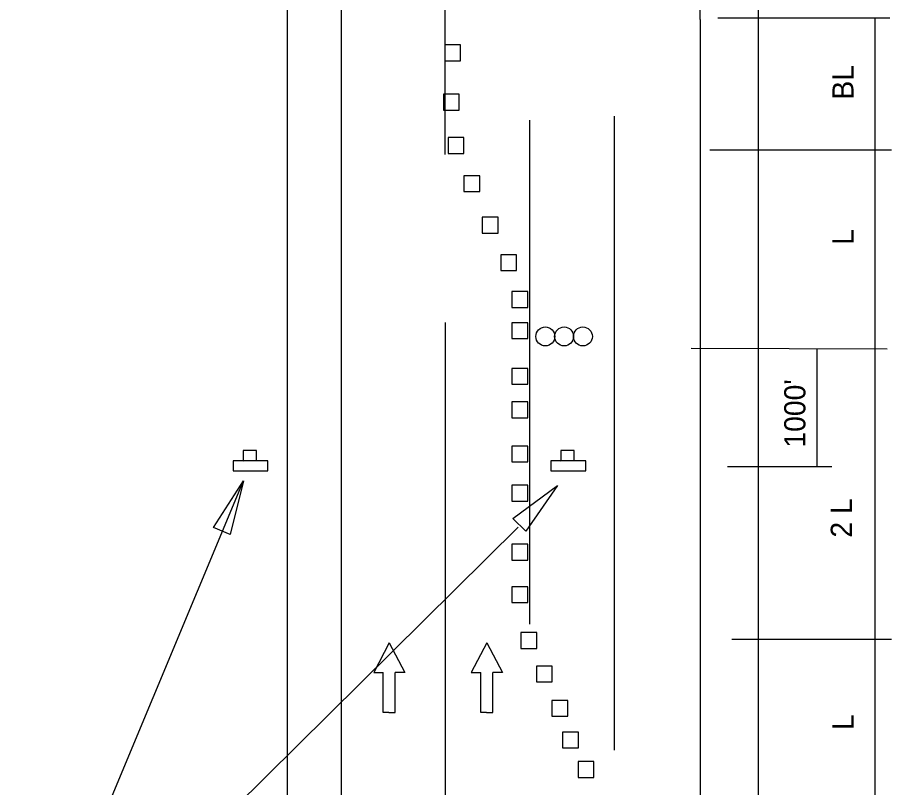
# Model space of a CAD drawing. Extents: x 1531.88 to 1538.58, y 1529.59 to 1539.31.
# Drawn here: x 1535.151 to 1537.629, y 1535.849 to 1538.033 of the extents above; entities that cross this region are included whole.
import ezdxf

# ---------------------------------------------------------------- set-up
doc = ezdxf.new("R2010")
doc.units = 0
for name, color, linetype in [('DETL-DIMS', 7, 'Continuous'), ('DETL-LINE', 7, 'Continuous'), ('DETL-NOTE', 7, 'Continuous'), ('USER-BORD', 7, 'Continuous')]:
    doc.layers.add(name, color=color, linetype=linetype)

# ---------------------------------------------------------------- blocks, each defined once
blk = doc.blocks.new('DIR2')
at = {"layer": 'USER-BORD'}
for p, q in [((0, 0.0012), (-0.0342, -0.0477)), ((0, 0.0012), (0.0342, -0.0477)), ((-0.0342, -0.0477), (-0.0132, -0.0477)), ((-0.0132, -0.1133), (-0.0132, -0.0477)), ((0.0342, -0.0477), (0.0132, -0.0477)), ((0.0132, -0.1133), (0.0132, -0.0477)), ((-0.0011, -0.1133), (-0.0132, -0.1133)), ((-0.0011, -0.1133), (0.0011, -0.1133)), ((0.0011, -0.1133), (0.0132, -0.1133))]:
    blk.add_line(p, q, dxfattribs=at)
blk = doc.blocks.new('PANEL0')
at = {"layer": 'USER-BORD'}
for centre in [(0.0309, -0.0012), (0.0928, -0.0012), (0.1546, -0.0012)]:
    blk.add_circle(centre, 0.0312, dxfattribs=at)
blk = doc.blocks.new('SIGN13')
at = {"layer": 'USER-BORD'}
for points in [[(-0.0134, 0.0182), (0.011, 0.0189), (0.011, 0.0371), (-0.0134, 0.0371)], [(-0.0314, 0.0182), (-0.0314, 0), (0.032, 0), (0.032, 0.0182)]]:
    blk.add_lwpolyline(points, close=True, dxfattribs=at)

msp = doc.modelspace()

# ---------------------------------------------------------------- linework, layer by layer
at = {"layer": 'DETL-DIMS'}
for p, q in [((1537.1366, 1538.0317), (1537.6237, 1538.0317)), ((1537.5814, 1538.0317), (1537.5814, 1534.7954)), ((1537.1135, 1537.6572), (1537.6288, 1537.6572)), ((1537.0607, 1537.0948), (1537.6168, 1537.0934)), ((1537.417, 1537.0934), (1537.417, 1536.7599)), ((1537.1635, 1536.7599), (1537.4593, 1536.7599)), ((1535.1506, 1535.1832), (1535.791, 1536.7191)), ((1536.5698, 1536.5877), (1535.1506, 1535.1832)), ((1537.1756, 1536.2703), (1537.6288, 1536.2703))]:
    msp.add_line(p, q, dxfattribs=at)
for points in [[(1535.754, 1536.5664), (1535.7065, 1536.5866), (1535.791, 1536.7191)], [(1536.5918, 1536.5762), (1536.5548, 1536.6122), (1536.6814, 1536.7054)]]:
    msp.add_lwpolyline(points, close=True, dxfattribs=at)
at = {"layer": 'DETL-LINE'}
for p, q in [((1535.9152, 1539.0264), (1535.9152, 1532.2422)), ((1536.0684, 1539.0264), (1536.0684, 1532.2422)), ((1536.3631, 1537.6445), (1536.3631, 1539.0264)), ((1537.2503, 1539.0264), (1537.2503, 1532.2422)), ((1537.0865, 1538.0273), (1537.0865, 1538.3858)), ((1537.0865, 1538.0273), (1537.0865, 1532.2422)), ((1536.8425, 1537.7535), (1536.8425, 1535.9549)), ((1536.6021, 1537.7415), (1536.6021, 1536.3125)), ((1536.3631, 1537.1676), (1536.3631, 1532.2422))]:
    msp.add_line(p, q, dxfattribs=at)
for points in [[(1536.3623, 1537.9104), (1536.4071, 1537.9104), (1536.4071, 1537.9552), (1536.3623, 1537.9552)], [(1536.3586, 1537.7705), (1536.4034, 1537.7705), (1536.4034, 1537.8153), (1536.3586, 1537.8153)], [(1536.3716, 1537.6473), (1536.4164, 1537.6473), (1536.4164, 1537.6921), (1536.3716, 1537.6921)], [(1536.4164, 1537.5391), (1536.4612, 1537.5391), (1536.4612, 1537.5839), (1536.4164, 1537.5839)], [(1536.4686, 1537.4216), (1536.5134, 1537.4216), (1536.5134, 1537.4664), (1536.4686, 1537.4664)], [(1536.5208, 1537.3153), (1536.5656, 1537.3153), (1536.5656, 1537.3601), (1536.5208, 1537.3601)], [(1536.5526, 1537.2108), (1536.5974, 1537.2108), (1536.5974, 1537.2556), (1536.5526, 1537.2556)], [(1536.5526, 1537.1227), (1536.5974, 1537.1227), (1536.5974, 1537.1675), (1536.5526, 1537.1675)], [(1536.5526, 1536.9932), (1536.5974, 1536.9932), (1536.5974, 1537.038), (1536.5526, 1537.038)], [(1536.5526, 1536.8981), (1536.5974, 1536.8981), (1536.5974, 1536.9429), (1536.5526, 1536.9429)], [(1536.5526, 1536.7728), (1536.5974, 1536.7728), (1536.5974, 1536.8176), (1536.5526, 1536.8176)], [(1536.5526, 1536.6615), (1536.5974, 1536.6615), (1536.5974, 1536.7063), (1536.5526, 1536.7063)], [(1536.5526, 1536.4944), (1536.5974, 1536.4944), (1536.5974, 1536.5392), (1536.5526, 1536.5392)], [(1536.5526, 1536.3737), (1536.5974, 1536.3737), (1536.5974, 1536.4185), (1536.5526, 1536.4185)], [(1536.5781, 1536.2439), (1536.6229, 1536.2439), (1536.6229, 1536.2887), (1536.5781, 1536.2887)], [(1536.6221, 1536.1487), (1536.6669, 1536.1487), (1536.6669, 1536.1935), (1536.6221, 1536.1935)], [(1536.6661, 1536.0513), (1536.7109, 1536.0513), (1536.7109, 1536.0961), (1536.6661, 1536.0961)], [(1536.6961, 1535.9615), (1536.7409, 1535.9615), (1536.7409, 1536.0063), (1536.6961, 1536.0063)], [(1536.7401, 1535.878), (1536.7849, 1535.878), (1536.7849, 1535.9228), (1536.7401, 1535.9228)]]:
    msp.add_lwpolyline(points, close=True, dxfattribs=at)
for points in [[(1536.3631, 1537.7945), (1536.3631, 1537.8945)], [(1536.8425, 1537.6035), (1536.8425, 1537.5035)], [(1536.6021, 1537.5915), (1536.6021, 1537.4915)], [(1536.8425, 1537.2035), (1536.8425, 1537.1035)], [(1536.6021, 1537.1915), (1536.6021, 1537.0915)], [(1536.3631, 1537.0176), (1536.3631, 1536.9176)], [(1536.6021, 1536.7915), (1536.6021, 1536.6915)], [(1536.8425, 1536.8035), (1536.8425, 1536.7035)], [(1536.3631, 1536.6176), (1536.3631, 1536.5176)], [(1536.6021, 1536.3915), (1536.6021, 1536.3125)], [(1536.8425, 1536.4035), (1536.8425, 1536.3035)], [(1536.3631, 1536.2176), (1536.3631, 1536.1176)], [(1536.8425, 1536.0035), (1536.8425, 1535.9549)]]:
    msp.add_lwpolyline(points, dxfattribs=at)

# ---------------------------------------------------------------- block references
for name, p, xscale, yscale in [('PANEL0', (1536.6206, 1537.1295), 0.8611764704, 0.8611764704), ('SIGN13', (1535.8109, 1536.7475), 1.554867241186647, 1.5548672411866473), ('SIGN13', (1536.7119, 1536.7475), 1.554867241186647, 1.5548672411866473), ('DIR2', (1536.2048, 1536.2573), 1.2917647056, 1.7223529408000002), ('DIR2', (1536.4814, 1536.2573), 1.2917647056, 1.7223529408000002)]:
    msp.add_blockref(name, p, dxfattribs=dict(at, xscale=xscale, yscale=yscale))

# ---------------------------------------------------------------- texts
at = {"layer": 'DETL-NOTE'}
for s, p in [('BL', (1537.5211, 1537.8)), ('L', (1537.5211, 1537.3883)), ("1000'", (1537.3846, 1536.8132)), ('2 L', (1537.5165, 1536.558)), ('L', (1537.5211, 1536.0123))]:
    msp.add_text(s, height=0.06, rotation=90, dxfattribs=at).set_placement(p)

doc.saveas('drawing.dxf')
